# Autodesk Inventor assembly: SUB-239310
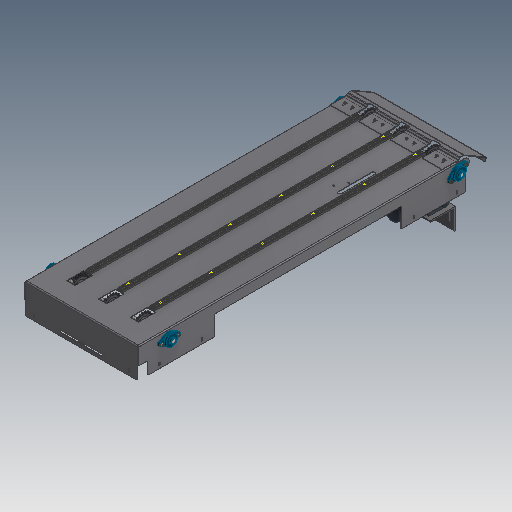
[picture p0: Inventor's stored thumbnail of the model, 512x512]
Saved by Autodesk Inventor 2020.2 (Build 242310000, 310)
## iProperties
Created: 2000-02
Part Number: SUB-239310
Document SubType Name: Assembly
Designer: sspink
Mass: 51277.9 g
Surface Area: 54043.3 cm^2
Volume: 12012.2 cm^3
Density: 4.26881 g/cm^3
Control State: 0
Checked Out: False
Master: False
Shininess: 0.0
Length Units: 11269
Angle Units: 11279
Time Units: 11290
Mass Units: 11283
Length Display Precision: 3
Angle Display Precision: 2
Compacted: True
Dimensions: 521,4x2089,1x746,5 mm
Mass: 51,278 kg
Density: 0.0
Volumn: 0.0
Area: 0.0
PropertySet Name: Model Information
Author: sspink
Revision Number: -
Title: SUB-239310
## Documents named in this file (25)
- D:\07 - DEMODATEN\OTX 2019 - Dataset - UPDATE - Dez2019\Designs\07-Packing machine\SUB-239310.iam
- D:\07 - DEMODATEN\OTX 2019 - Dataset - UPDATE - Dez2019\Designs\07-Packing machine\Parts\ADSK-011616.ipt
- D:\07 - DEMODATEN\OTX 2019 - Dataset - UPDATE - Dez2019\Designs\07-Packing machine\Parts\ADSK-011617.ipt
- D:\07 - DEMODATEN\OTX 2019 - Dataset - UPDATE - Dez2019\Designs\07-Packing machine\Parts\ADSK-011712.ipt
- D:\07 - DEMODATEN\OTX 2019 - Dataset - UPDATE - Dez2019\Designs\07-Packing machine\Parts\ADSK-011621.ipt
- D:\07 - DEMODATEN\OTX 2019 - Dataset - UPDATE - Dez2019\Designs\07-Packing machine\Parts\ADSK-011620.ipt
- D:\07 - DEMODATEN\OTX 2019 - Dataset - UPDATE - Dez2019\Designs\07-Packing machine\Parts\ADSK-011757.ipt
- D:\07 - DEMODATEN\OTX 2019 - Dataset - UPDATE - Dez2019\Designs\07-Packing machine\Parts\ADSK-011758.ipt
- D:\07 - DEMODATEN\OTX 2019 - Dataset - UPDATE - Dez2019\Designs\07-Packing machine\Parts\ADSK-011622.ipt
- D:\07 - DEMODATEN\OTX 2019 - Dataset - UPDATE - Dez2019\Designs\07-Packing machine\Parts\ADSK-011724.ipt
- D:\07 - DEMODATEN\OTX 2019 - Dataset - UPDATE - Dez2019\Designs\07-Packing machine\Parts\ADSK-011747.ipt
- D:\07 - DEMODATEN\OTX 2019 - Dataset - UPDATE - Dez2019\Designs\07-Packing machine\Parts\ADSK-011669.ipt
- D:\07 - DEMODATEN\OTX 2019 - Dataset - UPDATE - Dez2019\Designs\07-Packing machine\Parts\ADSK-011723.ipt
- D:\07 - DEMODATEN\OTX 2019 - Dataset - UPDATE - Dez2019\Content Center Files\de-DE\DIN 125-1  B\DIN 125-1 - B 7,4.ipt
- D:\07 - DEMODATEN\OTX 2019 - Dataset - UPDATE - Dez2019\Content Center Files\de-DE\ISO 4032(1)\ISO 4032 - M6DIN EN.ipt
- D:\07 - DEMODATEN\OTX 2019 - Dataset - UPDATE - Dez2019\Content Center Files\de-DE\DIN 125-1  B\DIN 125-1 - B 6,4.ipt
- D:\07 - DEMODATEN\OTX 2019 - Dataset - UPDATE - Dez2019\Content Center Files\de-DE\ISO 10642(1)\ISO 10642 - M6x16.ipt
- D:\07 - DEMODATEN\OTX 2019 - Dataset - UPDATE - Dez2019\Content Center Files\de-DE\ISO 4762(2)\ISO 4762 - M6 x 16ISO.ipt
- D:\07 - DEMODATEN\OTX 2019 - Dataset - UPDATE - Dez2019\Content Center Files\de-DE\DIN 125-1  B\DIN 125-1 - B 8,4.ipt
- D:\07 - DEMODATEN\OTX 2019 - Dataset - UPDATE - Dez2019\Content Center Files\de-DE\ISO 4032(1)\ISO 4032 - M8DIN EN.ipt
- D:\07 - DEMODATEN\OTX 2019 - Dataset - UPDATE - Dez2019\Content Center Files\de-DE\ISO 4762(2)\ISO 4762 - M8 x 30ISO.ipt
- D:\07 - DEMODATEN\OTX 2019 - Dataset - UPDATE - Dez2019\Content Center Files\de-DE\ISO 2491 - A\ISO 2491 - A  6 x 4 x 32.ipt
- D:\07 - DEMODATEN\OTX 2019 - Dataset - UPDATE - Dez2019\Content Center Files\de-DE\ISO 2491 - A\ISO 2491 - A  5 x 3 x 32.ipt
- D:\07 - DEMODATEN\OTX 2019 - Dataset - UPDATE - Dez2019\Content Center Files\de-DE\ISO 4026\ISO 4026 - M5 x 10 - ISO.ipt
- D:\07 - DEMODATEN\OTX 2019 - Dataset - UPDATE - Dez2019\Content Center Files\de-DE\ISO 4762(2)\ISO 4762 - M6 x 35ISO.ipt
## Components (164 placed, 24 different names)
1. ADSK-011617:1 — Passend:25, Passend:26, Passend:27, Fluchtend:12, Fluchtend:13, Fluchtend:14, Fluchtend:15, Fluchtend:16, Passend:29, Passend:31, Passend:33, Passend:35, Passend:37, Passend:39, Passend:41, Passend:43, Passend:45, Passend:47, Passend:49, Passend:51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
2. ADSK-011616:1 — Passend:26, Fluchtend:13, Fluchtend:14
3. ADSK-011616:2 — Passend:27, Fluchtend:12, Fluchtend:15
4. ADSK-011616:3 — Passend:25, Fluchtend:16
5. ADSK-011712:1 — Passend:126, Passend:127, Passend:128
6. ADSK-011712:2 — Passend:123, Passend:124, Passend:125, Passend:161
7. ADSK-011712:3 — Passend:117, Passend:118, Passend:119
8. ADSK-011712:4 — Passend:120, Passend:121, Passend:122, Passend:151
9. ADSK-011620:1 — Passend:146, Passend:147, Passend:148, Passend:149, Passend:151, Fluchtend:19, Fluchtend:20, Fluchtend:21, Passend:152, Passend:153, Passend:154, Passend:155, Passend:156, Passend:157, Passend:158, Passend:159, Passend:160, Passend:172, Passend:173, Passend:174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
10. ADSK-011621:1 — Mate:15, Mate:16, Mate:17, Passend:161, Fluchtend:22, Passend:163, Passend:164, Passend:165, Passend:166, Passend:167, Passend:168, Passend:169, Passend:170, Passend:171, Fluchtend:25, Fluchtend:26, Fluchtend:27
11. ADSK-011758:1 — Mate:15, Passend:162, Fluchtend:26
12. ADSK-011758:2 — Mate:16, Fluchtend:23, Fluchtend:25
13. ADSK-011758:3 — Mate:17, Fluchtend:24, Fluchtend:27
14. ADSK-011757:1 — Passend:147, Passend:150, Fluchtend:19
15. ADSK-011757:2 — Passend:148, Fluchtend:17, Fluchtend:20
16. ADSK-011757:3 — Passend:149, Fluchtend:18, Fluchtend:21
17. ADSK-011622:1 — Passend:82, Passend:83
18. ADSK-011724:1 — Flush:10, Passend:174, Fluchtend:30, Fluchtend:31, Fluchtend:32
19. ADSK-011747:1 — Mate:24, Flush:8, Passend:172, Passend:173, Passend:175, Passend:176, Passend:177, Passend:178, Passend:179, Passend:193
20. ADSK-011669:1 — Mate:24, Flush:8, Fluchtend:29, Winkel:1, Passend:186, Passend:188, Passend:190, Passend:192, Passend:193
21. ADSK-011723:1 — Flush:10, Passend:175, Fluchtend:31, Passend:176, Passend:180
22. DIN 125-1 B B 6,4:23
23. DIN 125-1 B B 6,4:24
24. DIN 125-1 B B 6,4:25
25. DIN 125-1 B B 6,4:26
26. DIN 125-1 B B 6,4:27 — Passend:186
27. DIN 125-1 B B 6,4:28 — Passend:188
28. DIN 125-1 B B 6,4:29 — Passend:190
29. DIN 125-1 B B 6,4:30 — Passend:192
30. DIN EN 24032 M6:33
31. DIN EN 24032 M6:34
32. DIN EN 24032 M6:35
33. DIN EN 24032 M6:36
34. ISO 4762 M6 x 35:1
35. ISO 4762 M6 x 35:2
36. ISO 4762 M6 x 35:3
37. ISO 4762 M6 x 35:4
38. ISO 2491 A A  6 x 4 x 32:4 — Passend:163, Passend:170, Passend:171
39. ISO 2491 A A  6 x 4 x 32:5 — Passend:164, Passend:168, Passend:169
40. ISO 2491 A A  6 x 4 x 32:6 — Passend:165, Passend:166, Passend:167
41. ISO 2491 A A  5 x 3 x 32:1 — Passend:177, Passend:178, Passend:179, Passend:181
42. ISO 4026 M5 x 10:1 — Passend:180, Passend:181
43. ISO 2491 A A  6 x 4 x 32:7 — Passend:182, Passend:183, Passend:184
44. ISO 2491 A A  6 x 4 x 32:1 — Passend:155, Passend:159, Passend:160
45. ISO 2491 A A  6 x 4 x 32:2 — Passend:152, Passend:153, Passend:154
46. ISO 2491 A A  6 x 4 x 32:3 — Passend:156, Passend:157, Passend:158
47. DIN 125-1 B B 8,4:1 — Passend:134, Passend:136
48. DIN 125-1 B B 8,4:2
49. DIN 125-1 B B 8,4:3 — Passend:138, Passend:140
50. DIN 125-1 B B 8,4:4
51. DIN 125-1 B B 8,4:5
52. DIN 125-1 B B 8,4:6 — Passend:130, Passend:132
53. DIN 125-1 B B 8,4:7
54. DIN 125-1 B B 8,4:8 — Passend:142, Passend:144
55. DIN 125-1 B B 8,4:9
56. DIN 125-1 B B 8,4:10
57. DIN 125-1 B B 8,4:11
58. DIN 125-1 B B 8,4:12
59. DIN 125-1 B B 8,4:13
60. DIN 125-1 B B 8,4:14
61. DIN 125-1 B B 8,4:15
62. DIN 125-1 B B 8,4:16
63. DIN EN 24032 M8:1
64. DIN EN 24032 M8:2
65. DIN EN 24032 M8:3
66. DIN EN 24032 M8:4
67. DIN EN 24032 M8:5
68. DIN EN 24032 M8:6
69. DIN EN 24032 M8:7
70. DIN EN 24032 M8:8
71. ISO 4762 M8 x 30:1 — Passend:130
72. ISO 4762 M8 x 30:2 — Passend:132
73. ISO 4762 M8 x 30:3 — Passend:134
74. ISO 4762 M8 x 30:4 — Passend:136
75. ISO 4762 M8 x 30:5 — Passend:138
76. ISO 4762 M8 x 30:6 — Passend:140
77. ISO 4762 M8 x 30:7 — Passend:142
78. ISO 4762 M8 x 30:8 — Passend:144
79. DIN 125-1 B B 6,4:7
80. DIN 125-1 B B 6,4:8
81. DIN 125-1 B B 6,4:9
82. DIN 125-1 B B 6,4:10
83. DIN 125-1 B B 6,4:11
84. DIN 125-1 B B 6,4:12
85. DIN 125-1 B B 6,4:13 — Passend:102, Passend:104, Passend:106, Passend:108, Passend:110, Passend:112, Passend:114, Passend:116
86. DIN 125-1 B B 6,4:14
87. DIN 125-1 B B 6,4:15 — Passend:86
88. DIN 125-1 B B 6,4:16 — Passend:88
89. DIN 125-1 B B 6,4:17 — Passend:90
90. DIN 125-1 B B 6,4:18 — Passend:92
91. DIN 125-1 B B 6,4:19 — Passend:94
92. DIN 125-1 B B 6,4:20 — Passend:96
93. DIN 125-1 B B 6,4:21 — Passend:98
94. DIN 125-1 B B 6,4:22 — Passend:100
95. DIN EN 24032 M6:25
96. DIN EN 24032 M6:26
97. DIN EN 24032 M6:27
98. DIN EN 24032 M6:28
99. DIN EN 24032 M6:29
100. DIN EN 24032 M6:30
101. ISO 4762 M6 x 16:1 — Passend:102
102. ISO 4762 M6 x 16:2 — Passend:104
103. ISO 4762 M6 x 16:3 — Passend:106
104. ISO 4762 M6 x 16:4 — Passend:108
105. ISO 4762 M6 x 16:5 — Passend:110
106. ISO 4762 M6 x 16:6 — Passend:112
107. ISO 4762 M6 x 16:7 — Passend:114
108. ISO 4762 M6 x 16:8 — Passend:116
109. DIN EN 24032 M6:31
110. DIN EN 24032 M6:32
111. DIN 125-1 B B 6,4:1 — Passend:53
112. DIN 125-1 B B 6,4:2 — Passend:55
113. DIN 125-1 B B 6,4:3 — Passend:57
114. DIN 125-1 B B 6,4:4 — Passend:59
115. DIN 125-1 B B 6,4:5 — Passend:61
116. DIN 125-1 B B 6,4:6 — Passend:63
117. DIN EN 24032 M6:19
118. DIN EN 24032 M6:20
119. DIN EN 24032 M6:21
120. DIN EN 24032 M6:22
121. DIN EN 24032 M6:23
122. DIN EN 24032 M6:24
123. ISO 10642 M6x16:1
124. ISO 10642 M6x16:2
125. ISO 10642 M6x16:3
126. ISO 10642 M6x16:4
127. ISO 10642 M6x16:5
128. ISO 10642 M6x16:6
129. ISO 10642 M6x16:7
130. ISO 10642 M6x16:8
131. ISO 10642 M6x16:9
132. ISO 10642 M6x16:10
133. ISO 10642 M6x16:11
134. ISO 10642 M6x16:12
135. ISO 10642 M6x16:13
136. ISO 10642 M6x16:14
137. ISO 10642 M6x16:15
138. ISO 10642 M6x16:16
139. ISO 10642 M6x16:17
140. ISO 10642 M6x16:18
141. DIN EN 24032 M6:7
142. DIN EN 24032 M6:10
143. DIN EN 24032 M6:12
144. DIN EN 24032 M6:14
145. DIN EN 24032 M6:15
146. DIN EN 24032 M6:18
147. DIN 125-1 B B 7,4:1 — Passend:29
148. DIN 125-1 B B 7,4:2 — Passend:31
149. DIN 125-1 B B 7,4:3 — Passend:33
150. DIN 125-1 B B 7,4:4 — Passend:35
151. DIN 125-1 B B 7,4:5 — Passend:37
152. DIN 125-1 B B 7,4:6 — Passend:39
153. DIN EN 24032 M6:1
154. DIN EN 24032 M6:2
155. DIN EN 24032 M6:3
156. DIN EN 24032 M6:4
157. DIN EN 24032 M6:5
158. DIN EN 24032 M6:6
159. DIN 125-1 B B 7,4:7 — Passend:41
160. DIN 125-1 B B 7,4:8 — Passend:43
161. DIN 125-1 B B 7,4:9 — Passend:45
162. DIN 125-1 B B 7,4:10 — Passend:47
163. DIN 125-1 B B 7,4:11 — Passend:49
164. DIN 125-1 B B 7,4:12 — Passend:51
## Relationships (130: Mate 107, Flush 22, Angle 1)
- Mate:15: ADSK-011621:1 ↔ ADSK-011758:1
- Mate:16: ADSK-011621:1 ↔ ADSK-011758:2
- Mate:17: ADSK-011621:1 ↔ ADSK-011758:3
- Mate:24: ADSK-011747:1 ↔ ADSK-011669:1
- Flush:8: ADSK-011747:1 ↔ ADSK-011669:1
- Flush:10: ADSK-011724:1 ↔ ADSK-011723:1
- Passend:25 [Mate]: ADSK-011617:1 ↔ ADSK-011616:3
- Passend:26 [Mate]: ADSK-011617:1 ↔ ADSK-011616:1
- Passend:27 [Mate]: ADSK-011617:1 ↔ ADSK-011616:2
- Fluchtend:12 [Flush]: ADSK-011617:1 ↔ ADSK-011616:2
- Fluchtend:13 [Flush]: ADSK-011617:1 ↔ ADSK-011616:1
- Fluchtend:14 [Flush]: ADSK-011617:1 ↔ ADSK-011616:1
- Fluchtend:15 [Flush]: ADSK-011617:1 ↔ ADSK-011616:2
- Fluchtend:16 [Flush]: ADSK-011617:1 ↔ ADSK-011616:3
- Passend:29 [Mate]: ADSK-011617:1 ↔ DIN 125-1 B B 7,4:1
- Passend:31 [Mate]: ADSK-011617:1 ↔ DIN 125-1 B B 7,4:2
- Passend:33 [Mate]: ADSK-011617:1 ↔ DIN 125-1 B B 7,4:3
- Passend:35 [Mate]: ADSK-011617:1 ↔ DIN 125-1 B B 7,4:4
- Passend:37 [Mate]: ADSK-011617:1 ↔ DIN 125-1 B B 7,4:5
- Passend:39 [Mate]: ADSK-011617:1 ↔ DIN 125-1 B B 7,4:6
- Passend:41 [Mate]: ADSK-011617:1 ↔ DIN 125-1 B B 7,4:7
- Passend:43 [Mate]: ADSK-011617:1 ↔ DIN 125-1 B B 7,4:8
- Passend:45 [Mate]: ADSK-011617:1 ↔ DIN 125-1 B B 7,4:9
- Passend:47 [Mate]: ADSK-011617:1 ↔ DIN 125-1 B B 7,4:10
- Passend:49 [Mate]: ADSK-011617:1 ↔ DIN 125-1 B B 7,4:11
- Passend:51 [Mate]: ADSK-011617:1 ↔ DIN 125-1 B B 7,4:12
- Passend:53 [Mate]: ADSK-011617:1 ↔ DIN 125-1 B B 6,4:1
- Passend:55 [Mate]: ADSK-011617:1 ↔ DIN 125-1 B B 6,4:2
- Passend:57 [Mate]: ADSK-011617:1 ↔ DIN 125-1 B B 6,4:3
- Passend:59 [Mate]: ADSK-011617:1 ↔ DIN 125-1 B B 6,4:4
- Passend:61 [Mate]: ADSK-011617:1 ↔ DIN 125-1 B B 6,4:5
- Passend:63 [Mate]: ADSK-011617:1 ↔ DIN 125-1 B B 6,4:6
- Passend:82 [Mate]: ADSK-011617:1 ↔ ADSK-011622:1
- Passend:83 [Mate]: ADSK-011617:1 ↔ ADSK-011622:1
- Passend:86 [Mate]: ADSK-011617:1 ↔ DIN 125-1 B B 6,4:15
- Passend:88 [Mate]: ADSK-011617:1 ↔ DIN 125-1 B B 6,4:16
- Passend:90 [Mate]: ADSK-011617:1 ↔ DIN 125-1 B B 6,4:17
- Passend:92 [Mate]: ADSK-011617:1 ↔ DIN 125-1 B B 6,4:18
- Passend:94 [Mate]: ADSK-011617:1 ↔ DIN 125-1 B B 6,4:19
- Passend:96 [Mate]: ADSK-011617:1 ↔ DIN 125-1 B B 6,4:20
- Passend:98 [Mate]: ADSK-011617:1 ↔ DIN 125-1 B B 6,4:21
- Passend:100 [Mate]: ADSK-011617:1 ↔ DIN 125-1 B B 6,4:22
- Passend:102 [Mate]: DIN 125-1 B B 6,4:13 ↔ ISO 4762 M6 x 16:1
- Passend:104 [Mate]: DIN 125-1 B B 6,4:13 ↔ ISO 4762 M6 x 16:2
- Passend:106 [Mate]: DIN 125-1 B B 6,4:13 ↔ ISO 4762 M6 x 16:3
- Passend:108 [Mate]: DIN 125-1 B B 6,4:13 ↔ ISO 4762 M6 x 16:4
- Passend:110 [Mate]: DIN 125-1 B B 6,4:13 ↔ ISO 4762 M6 x 16:5
- Passend:112 [Mate]: DIN 125-1 B B 6,4:13 ↔ ISO 4762 M6 x 16:6
- Passend:114 [Mate]: DIN 125-1 B B 6,4:13 ↔ ISO 4762 M6 x 16:7
- Passend:116 [Mate]: DIN 125-1 B B 6,4:13 ↔ ISO 4762 M6 x 16:8
- Passend:117 [Mate]: ADSK-011617:1 ↔ ADSK-011712:3
- Passend:118 [Mate]: ADSK-011617:1 ↔ ADSK-011712:3
- Passend:119 [Mate]: ADSK-011617:1 ↔ ADSK-011712:3
- Passend:120 [Mate]: ADSK-011617:1 ↔ ADSK-011712:4
- Passend:121 [Mate]: ADSK-011617:1 ↔ ADSK-011712:4
- Passend:122 [Mate]: ADSK-011617:1 ↔ ADSK-011712:4
- Passend:123 [Mate]: ADSK-011617:1 ↔ ADSK-011712:2
- Passend:124 [Mate]: ADSK-011617:1 ↔ ADSK-011712:2
- Passend:125 [Mate]: ADSK-011617:1 ↔ ADSK-011712:2
- Passend:126 [Mate]: ADSK-011617:1 ↔ ADSK-011712:1
- Passend:127 [Mate]: ADSK-011617:1 ↔ ADSK-011712:1
- Passend:128 [Mate]: ADSK-011617:1 ↔ ADSK-011712:1
- Passend:130 [Mate]: DIN 125-1 B B 8,4:6 ↔ ISO 4762 M8 x 30:1
- Passend:132 [Mate]: DIN 125-1 B B 8,4:6 ↔ ISO 4762 M8 x 30:2
- Passend:134 [Mate]: DIN 125-1 B B 8,4:1 ↔ ISO 4762 M8 x 30:3
- Passend:136 [Mate]: DIN 125-1 B B 8,4:1 ↔ ISO 4762 M8 x 30:4
- Passend:138 [Mate]: DIN 125-1 B B 8,4:3 ↔ ISO 4762 M8 x 30:5
- Passend:140 [Mate]: DIN 125-1 B B 8,4:3 ↔ ISO 4762 M8 x 30:6
- Passend:142 [Mate]: DIN 125-1 B B 8,4:8 ↔ ISO 4762 M8 x 30:7
- Passend:144 [Mate]: DIN 125-1 B B 8,4:8 ↔ ISO 4762 M8 x 30:8
- Passend:146 [Mate]: ADSK-011620:1
- Passend:147 [Mate]: ADSK-011620:1 ↔ ADSK-011757:1
- Passend:148 [Mate]: ADSK-011620:1 ↔ ADSK-011757:2
- Passend:149 [Mate]: ADSK-011620:1 ↔ ADSK-011757:3
- Passend:150 [Mate]: ADSK-011617:1 ↔ ADSK-011757:1
- Fluchtend:17 [Flush]: ADSK-011757:2
- Fluchtend:18 [Flush]: ADSK-011617:1 ↔ ADSK-011757:3
- Passend:151 [Mate]: ADSK-011712:4 ↔ ADSK-011620:1
- Fluchtend:19 [Flush]: ADSK-011620:1 ↔ ADSK-011757:1
- Fluchtend:20 [Flush]: ADSK-011620:1 ↔ ADSK-011757:2
- Fluchtend:21 [Flush]: ADSK-011620:1 ↔ ADSK-011757:3
- Passend:152 [Mate]: ADSK-011620:1 ↔ ISO 2491 A A  6 x 4 x 32:2
- Passend:153 [Mate]: ADSK-011620:1 ↔ ISO 2491 A A  6 x 4 x 32:2
- Passend:154 [Mate]: ADSK-011620:1 ↔ ISO 2491 A A  6 x 4 x 32:2
- Passend:155 [Mate]: ADSK-011620:1 ↔ ISO 2491 A A  6 x 4 x 32:1
- Passend:156 [Mate]: ADSK-011620:1 ↔ ISO 2491 A A  6 x 4 x 32:3
- Passend:157 [Mate]: ADSK-011620:1 ↔ ISO 2491 A A  6 x 4 x 32:3
- Passend:158 [Mate]: ADSK-011620:1 ↔ ISO 2491 A A  6 x 4 x 32:3
- Passend:159 [Mate]: ADSK-011620:1 ↔ ISO 2491 A A  6 x 4 x 32:1
- Passend:160 [Mate]: ADSK-011620:1 ↔ ISO 2491 A A  6 x 4 x 32:1
- Passend:161 [Mate]: ADSK-011712:2 ↔ ADSK-011621:1
- Fluchtend:22 [Flush]: ADSK-011621:1
- Passend:162 [Mate]: ADSK-011617:1 ↔ ADSK-011758:1
- Fluchtend:23 [Flush]: ADSK-011758:2
- Fluchtend:24 [Flush]: ADSK-011617:1 ↔ ADSK-011758:3
- Passend:163 [Mate]: ADSK-011621:1 ↔ ISO 2491 A A  6 x 4 x 32:4
- Passend:164 [Mate]: ADSK-011621:1 ↔ ISO 2491 A A  6 x 4 x 32:5
- Passend:165 [Mate]: ADSK-011621:1 ↔ ISO 2491 A A  6 x 4 x 32:6
- Passend:166 [Mate]: ADSK-011621:1 ↔ ISO 2491 A A  6 x 4 x 32:6
- Passend:167 [Mate]: ADSK-011621:1 ↔ ISO 2491 A A  6 x 4 x 32:6
- Passend:168 [Mate]: ADSK-011621:1 ↔ ISO 2491 A A  6 x 4 x 32:5
- Passend:169 [Mate]: ADSK-011621:1 ↔ ISO 2491 A A  6 x 4 x 32:5
- Passend:170 [Mate]: ADSK-011621:1 ↔ ISO 2491 A A  6 x 4 x 32:4
- Passend:171 [Mate]: ADSK-011621:1 ↔ ISO 2491 A A  6 x 4 x 32:4
- Fluchtend:25 [Flush]: ADSK-011621:1 ↔ ADSK-011758:2
- Fluchtend:26 [Flush]: ADSK-011621:1 ↔ ADSK-011758:1
- Fluchtend:27 [Flush]: ADSK-011621:1 ↔ ADSK-011758:3
- Fluchtend:29 [Flush]: ADSK-011669:1
- Winkel:1 [Angle]: ADSK-011617:1 ↔ ADSK-011669:1
- Passend:172 [Mate]: ADSK-011620:1 ↔ ADSK-011747:1
- Passend:173 [Mate]: ADSK-011620:1 ↔ ADSK-011747:1
- Passend:174 [Mate]: ADSK-011620:1 ↔ ADSK-011724:1
- Fluchtend:30 [Flush]: ADSK-011724:1
- Passend:175 [Mate]: ADSK-011747:1 ↔ ADSK-011723:1
- Fluchtend:31 [Flush]: ADSK-011724:1 ↔ ADSK-011723:1
- Passend:176 [Mate]: ADSK-011747:1 ↔ ADSK-011723:1
- Passend:177 [Mate]: ADSK-011747:1 ↔ ISO 2491 A A  5 x 3 x 32:1
- Passend:178 [Mate]: ADSK-011747:1 ↔ ISO 2491 A A  5 x 3 x 32:1
- Passend:179 [Mate]: ADSK-011747:1 ↔ ISO 2491 A A  5 x 3 x 32:1
- Passend:180 [Mate]: ADSK-011723:1 ↔ ISO 4026 M5 x 10:1
- Passend:181 [Mate]: ISO 2491 A A  5 x 3 x 32:1 ↔ ISO 4026 M5 x 10:1
- Fluchtend:32 [Flush]: ADSK-011620:1 ↔ ADSK-011724:1
- Passend:182 [Mate]: ADSK-011620:1 ↔ ISO 2491 A A  6 x 4 x 32:7
- Passend:183 [Mate]: ADSK-011620:1 ↔ ISO 2491 A A  6 x 4 x 32:7
- Passend:184 [Mate]: ADSK-011620:1 ↔ ISO 2491 A A  6 x 4 x 32:7
- Passend:186 [Mate]: ADSK-011669:1 ↔ DIN 125-1 B B 6,4:27
- Passend:188 [Mate]: ADSK-011669:1 ↔ DIN 125-1 B B 6,4:28
- Passend:190 [Mate]: ADSK-011669:1 ↔ DIN 125-1 B B 6,4:29
- Passend:192 [Mate]: ADSK-011669:1 ↔ DIN 125-1 B B 6,4:30
- Passend:193 [Mate]: ADSK-011747:1 ↔ ADSK-011669:1
